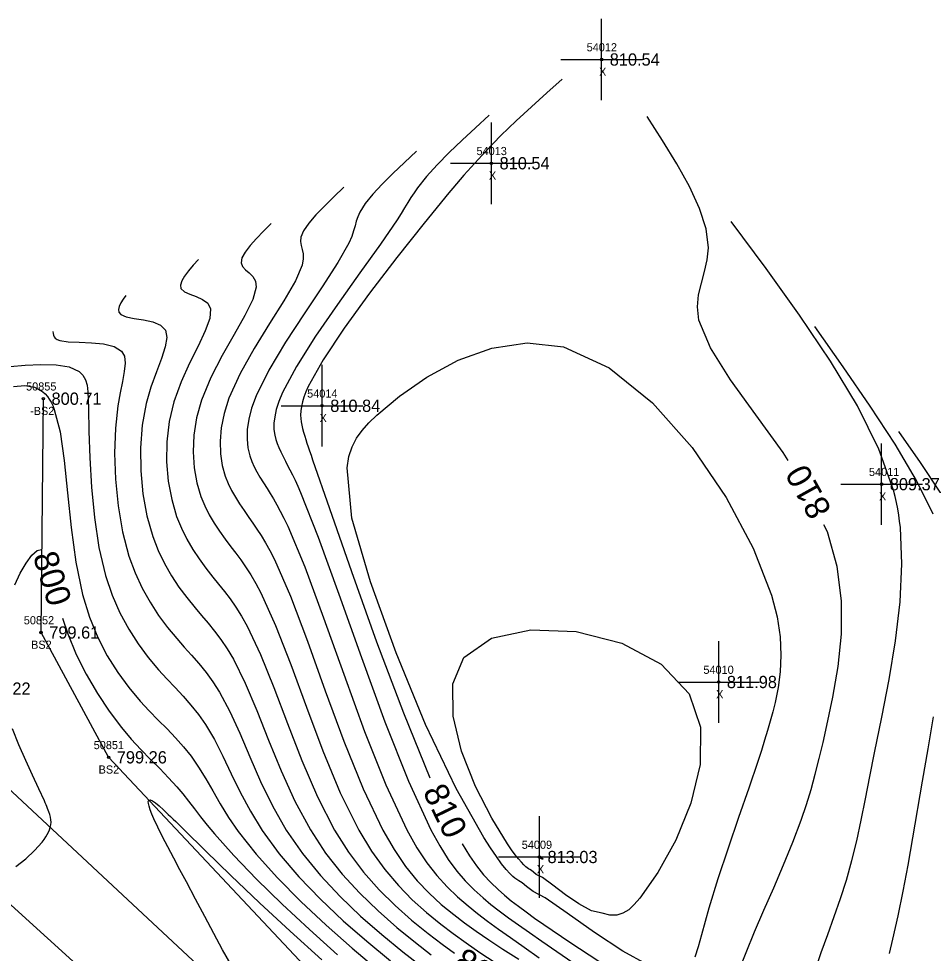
# Model space of a CAD drawing. Extents: x 1378535 to 1380697, y 997729 to 1000024.
# Drawn here: x 1378635.2 to 1378746.7, y 999909.1 to 1000023.6 of the extents above; entities that cross this region are included whole.
import ezdxf

# ---------------------------------------------------------------- set-up
doc = ezdxf.new("R2010")
doc.units = 0
for name, color, linetype in [('RD_DTM_BkLn1', 7, 'Continuous'), ('RD_DTM_BkLn2', 7, 'Continuous'), ('RD_DTM_BkLn_txCode', 7, 'Continuous'), ('RD_DTM_Major1', 7, 'Continuous'), ('RD_DTM_Major1_Lbl', 7, 'Continuous'), ('RD_DTM_Minor1', 7, 'Continuous'), ('RD_EX_Misc', 7, 'Continuous'), ('RD_EX_Misc_txCode', 7, 'Continuous'), ('RD_EX_Road', 7, 'Continuous'), ('RD_EX_TX_Misc_ELEV', 7, 'Continuous'), ('RD_SMD_Locator', 7, 'Continuous')]:
    doc.layers.add(name, color=color, linetype=linetype)

msp = doc.modelspace()

# ---------------------------------------------------------------- linework, layer by layer
at = {"layer": 'RD_DTM_BkLn1'}
msp.add_lwpolyline([(1379201.7, 999398.21), (1379156.53, 999438.89), (1379112.08, 999479.85), (1379066.5, 999520.56), (1379020.82, 999562.61), (1378974.24, 999604.98), (1378928.96, 999646.78), (1378882.74, 999688.62), (1378834.58, 999733.07), (1378787.7, 999775.12), (1378743.64, 999816.27), (1378698.71, 999856.43), (1378652.06, 999898.79), (1378607.02, 999939.65), (1378604.54, 999941.27)], dxfattribs=at)
at = {"layer": 'RD_DTM_BkLn2'}
msp.add_lwpolyline([(1378843.62, 999885.07), (1378833.28, 999869.8), (1378802.97, 999829.09), (1378773.74, 999822.49), (1378758.68, 999830.54), (1378715.18, 999866.67), (1378674.59, 999902.83), (1378646.18, 999933.08), (1378637.9, 999948.38), (1378638.18, 999977.04)], dxfattribs=at)
at = {"layer": 'RD_DTM_Major1'}
for points in [[(1378701.77, 1000016.22), (1378699.89, 1000014.53), (1378698.01, 1000012.83), (1378696.14, 1000011.09), (1378694.28, 1000009.29), (1378692.44, 1000007.4), (1378690.61, 1000005.43), (1378690.18, 1000004.93), (1378689.73, 1000004.42), (1378689.29, 1000003.91), (1378688.84, 1000003.37), (1378688.37, 1000002.83), (1378687.9, 1000002.26), (1378684.85, 999998.54), (1378681.51, 999994.36), (1378678.16, 999989.99), (1378675.06, 999985.7), (1378672.47, 999981.79), (1378670.66, 999978.54), (1378670.35, 999977.86), (1378670.11, 999977.23), (1378669.93, 999976.64), (1378669.81, 999976.08), (1378669.74, 999975.54), (1378669.72, 999975.01), (1378669.74, 999974.62), (1378669.78, 999974.22), (1378669.86, 999973.8), (1378669.95, 999973.37), (1378670.07, 999972.92), (1378670.22, 999972.43), (1378670.35, 999972.02), (1378670.49, 999971.59), (1378670.65, 999971.13), (1378670.82, 999970.63), (1378671, 999970.11), (1378671.19, 999969.55), (1378673.25, 999963.58), (1378675.94, 999955.87), (1378679.03, 999947.23), (1378682.32, 999938.51), (1378685.56, 999930.56)], [(1378729.51, 999969.45), (1378728.87, 999970.46), (1378725.55, 999975.06), (1378722.44, 999979.36), (1378719.96, 999983.26), (1378718.56, 999986.67), (1378718.38, 999988.29), (1378718.52, 999989.79), (1378718.85, 999991.22), (1378719.25, 999992.62), (1378719.58, 999994.05), (1378719.73, 999995.54), (1378719.44, 999997.85), (1378718.63, 1000000.37), (1378717.4, 1000003.04), (1378715.84, 1000005.83), (1378714.08, 1000008.7), (1378712.21, 1000011.62)], [(1378657.19, 999994.11), (1378656.56, 999993.41), (1378655.98, 999992.72), (1378655.49, 999992.07), (1378655.14, 999991.48), (1378654.98, 999990.96), (1378655.05, 999990.53), (1378655.47, 999990.15), (1378656.14, 999989.85), (1378656.93, 999989.56), (1378657.7, 999989.21), (1378658.33, 999988.74), (1378658.68, 999988.06), (1378658.6, 999986.88), (1378658.03, 999985.34), (1378657.15, 999983.49), (1378656.11, 999981.39), (1378655.07, 999979.1), (1378654.19, 999976.66), (1378653.62, 999974.23), (1378653.33, 999971.76), (1378653.29, 999969.31), (1378653.5, 999966.94), (1378653.91, 999964.68), (1378654.52, 999962.6), (1378655.1, 999961.15), (1378655.76, 999959.82), (1378656.49, 999958.57), (1378657.28, 999957.39), (1378658.11, 999956.27), (1378658.97, 999955.17), (1378659.67, 999954.31), (1378660.37, 999953.42), (1378661.07, 999952.49), (1378661.78, 999951.49), (1378662.48, 999950.38), (1378663.18, 999949.15), (1378664.81, 999945.7), (1378666.43, 999941.64), (1378668.11, 999937.22), (1378669.88, 999932.67), (1378671.79, 999928.23), (1378673.88, 999924.16), (1378675.6, 999921.43), (1378677.43, 999919.01), (1378679.34, 999916.85), (1378681.32, 999914.9), (1378683.33, 999913.13), (1378685.36, 999911.49), (1378687.07, 999910.17), (1378688.6, 999909.05)], [(1378723.7, 999907.53), (1378724.34, 999909.16), (1378725.38, 999911.67), (1378726.53, 999914.33), (1378727.73, 999917.08), (1378728.93, 999919.88), (1378730.06, 999922.66), (1378731.08, 999925.37), (1378731.73, 999927.28), (1378732.3, 999929.15), (1378732.82, 999931.03), (1378733.3, 999932.93), (1378733.77, 999934.9), (1378734.23, 999936.96), (1378734.98, 999940.46), (1378735.62, 999944.21), (1378736.02, 999948.17), (1378736.02, 999952.28), (1378735.5, 999956.47), (1378734.3, 999960.7), (1378733.87, 999961.59)], [(1378634.67, 999954.21), (1378635.35, 999955.64), (1378636.07, 999956.89), (1378636.78, 999957.85), (1378637.43, 999958.44), (1378637.93, 999958.56)], [(1378640.53, 999950.13), (1378641.17, 999948.22), (1378642.22, 999945.7), (1378643.44, 999943.26), (1378644.8, 999940.91), (1378646.24, 999938.72), (1378647.74, 999936.74), (1378648.94, 999935.32), (1378650.13, 999934.03), (1378651.31, 999932.83), (1378652.44, 999931.69), (1378653.53, 999930.57), (1378654.56, 999929.45), (1378655.29, 999928.59), (1378655.99, 999927.7), (1378656.71, 999926.77), (1378657.46, 999925.8), (1378658.27, 999924.78), (1378659.16, 999923.69), (1378661.52, 999921.04), (1378664.32, 999918.14), (1378667.44, 999915.09), (1378670.79, 999911.96), (1378674.25, 999908.88)], [(1378634.8, 999919.69), (1378636.01, 999920.65), (1378637.1, 999921.67), (1378638.02, 999922.68), (1378638.26, 999923), (1378638.47, 999923.31), (1378638.66, 999923.62), (1378638.81, 999923.91), (1378638.94, 999924.2), (1378639.03, 999924.48), (1378639.1, 999924.8), (1378639.12, 999925.12), (1378639.11, 999925.43), (1378639.06, 999925.75), (1378638.97, 999926.07), (1378638.86, 999926.41), (1378638.78, 999926.61), (1378638.7, 999926.82), (1378638.61, 999927.04), (1378638.51, 999927.27), (1378638.41, 999927.5), (1378638.3, 999927.75), (1378637.62, 999929.2), (1378636.85, 999930.88), (1378636.01, 999932.7), (1378635.18, 999934.62), (1378634.4, 999936.57)], [(1378689.51, 999922.47), (1378689.51, 999922.46), (1378690.41, 999921.01), (1378691.29, 999919.76), (1378692.16, 999918.69), (1378693.03, 999917.74), (1378693.93, 999916.87), (1378694.71, 999916.18), (1378695.54, 999915.5), (1378696.42, 999914.82), (1378697.38, 999914.12), (1378698.41, 999913.38), (1378699.54, 999912.59), (1378702.71, 999910.41), (1378706.28, 999908.08)]]:
    msp.add_lwpolyline(points, dxfattribs=at)
at = {"layer": 'RD_DTM_Minor1'}
for points in [[(1378692.85, 1000011.79), (1378691.16, 1000010.25), (1378689.51, 1000008.72), (1378687.93, 1000007.21), (1378686.47, 1000005.72), (1378685.16, 1000004.28), (1378684.05, 1000002.88), (1378683.64, 1000002.28), (1378683.25, 1000001.69), (1378682.86, 1000001.07), (1378682.46, 1000000.42), (1378682.03, 999999.73), (1378681.54, 999998.97), (1378679.51, 999995.99), (1378676.98, 999992.45), (1378674.24, 999988.59), (1378671.56, 999984.69), (1378669.23, 999981), (1378667.51, 999977.78), (1378667.06, 999976.7), (1378666.74, 999975.72), (1378666.54, 999974.83), (1378666.44, 999974.02), (1378666.45, 999973.26), (1378666.54, 999972.56), (1378666.66, 999972.05), (1378666.83, 999971.55), (1378667.04, 999971.05), (1378667.28, 999970.53), (1378667.56, 999969.97), (1378667.87, 999969.38), (1378668.13, 999968.86), (1378668.41, 999968.31), (1378668.71, 999967.7), (1378669.03, 999967.04), (1378669.36, 999966.32), (1378669.72, 999965.52), (1378671.87, 999960.06), (1378674.4, 999953.09), (1378677.17, 999945.31), (1378680.06, 999937.43), (1378682.94, 999930.15), (1378685.68, 999924.18), (1378686.77, 999922.22), (1378687.82, 999920.56), (1378688.87, 999919.14), (1378689.91, 999917.93), (1378690.98, 999916.85), (1378692.08, 999915.86), (1378693.05, 999915.05), (1378694.08, 999914.25), (1378695.2, 999913.42), (1378696.42, 999912.55), (1378697.77, 999911.6), (1378699.28, 999910.55), (1378703.62, 999907.56)], [(1378683.94, 1000007.37), (1378682.46, 1000006), (1378681.04, 1000004.66), (1378679.73, 1000003.35), (1378678.58, 1000002.11), (1378677.64, 1000000.96), (1378676.98, 999999.91), (1378676.73, 999999.34), (1378676.54, 999998.79), (1378676.39, 999998.22), (1378676.22, 999997.6), (1378675.98, 999996.92), (1378675.65, 999996.12), (1378674.3, 999993.73), (1378672.38, 999990.77), (1378670.14, 999987.45), (1378667.86, 999983.98), (1378665.81, 999980.55), (1378664.25, 999977.37), (1378663.71, 999975.88), (1378663.36, 999974.51), (1378663.18, 999973.25), (1378663.15, 999972.09), (1378663.26, 999971.03), (1378663.48, 999970.05), (1378663.72, 999969.36), (1378664.01, 999968.7), (1378664.35, 999968.06), (1378664.73, 999967.41), (1378665.15, 999966.73), (1378665.61, 999966.02), (1378665.99, 999965.41), (1378666.38, 999964.76), (1378666.8, 999964.04), (1378667.23, 999963.26), (1378667.68, 999962.39), (1378668.14, 999961.42), (1378670.22, 999956.43), (1378672.53, 999950.19), (1378675, 999943.27), (1378677.57, 999936.25), (1378680.17, 999929.69), (1378682.74, 999924.18), (1378683.98, 999922), (1378685.21, 999920.15), (1378686.43, 999918.57), (1378687.68, 999917.2), (1378688.95, 999915.99), (1378690.26, 999914.86), (1378691.41, 999913.94), (1378692.64, 999913.01), (1378693.97, 999912.03), (1378695.45, 999910.98), (1378697.11, 999909.82), (1378698.98, 999908.51)], [(1378675.02, 1000002.95), (1378673.8, 1000001.79), (1378672.64, 1000000.65), (1378671.6, 999999.56), (1378670.72, 999998.54), (1378670.09, 999997.62), (1378669.74, 999996.82), (1378669.69, 999996.3), (1378669.77, 999995.82), (1378669.9, 999995.34), (1378670.02, 999994.8), (1378670.05, 999994.17), (1378669.92, 999993.4), (1378669.09, 999991.48), (1378667.67, 999989.04), (1378665.91, 999986.24), (1378664.04, 999983.21), (1378662.29, 999980.12), (1378660.93, 999977.09), (1378660.34, 999975.24), (1378659.99, 999973.48), (1378659.85, 999971.82), (1378659.9, 999970.28), (1378660.11, 999968.85), (1378660.47, 999967.54), (1378660.83, 999966.63), (1378661.24, 999965.77), (1378661.72, 999964.95), (1378662.24, 999964.14), (1378662.8, 999963.33), (1378663.39, 999962.49), (1378663.87, 999961.8), (1378664.37, 999961.06), (1378664.89, 999960.26), (1378665.42, 999959.38), (1378665.96, 999958.41), (1378666.52, 999957.32), (1378668.47, 999952.82), (1378670.55, 999947.31), (1378672.74, 999941.24), (1378675.02, 999935.06), (1378677.38, 999929.21), (1378679.78, 999924.15), (1378681.17, 999921.76), (1378682.58, 999919.71), (1378684.01, 999917.95), (1378685.46, 999916.41), (1378686.96, 999915.05), (1378688.49, 999913.79), (1378689.82, 999912.77), (1378691.24, 999911.75), (1378692.78, 999910.69), (1378694.51, 999909.56), (1378696.46, 999908.32)], [(1378666.1, 999998.53), (1378665.17, 999997.59), (1378664.29, 999996.67), (1378663.52, 999995.8), (1378662.91, 999995), (1378662.53, 999994.29), (1378662.42, 999993.69), (1378662.59, 999993.23), (1378662.96, 999992.84), (1378663.41, 999992.45), (1378663.85, 999992), (1378664.17, 999991.45), (1378664.27, 999990.72), (1378663.85, 999989.19), (1378662.89, 999987.22), (1378661.57, 999984.91), (1378660.11, 999982.35), (1378658.71, 999979.64), (1378657.57, 999976.87), (1378656.97, 999974.7), (1378656.64, 999972.57), (1378656.55, 999970.52), (1378656.67, 999968.56), (1378657, 999966.73), (1378657.49, 999965.05), (1378657.96, 999963.89), (1378658.5, 999962.8), (1378659.1, 999961.78), (1378659.76, 999960.8), (1378660.45, 999959.83), (1378661.18, 999958.87), (1378661.77, 999958.09), (1378662.37, 999957.28), (1378662.98, 999956.41), (1378663.6, 999955.46), (1378664.23, 999954.4), (1378664.86, 999953.23), (1378666.65, 999949.25), (1378668.5, 999944.47), (1378670.43, 999939.24), (1378672.45, 999933.87), (1378674.58, 999928.73), (1378676.84, 999924.14), (1378678.41, 999921.56), (1378680.03, 999919.32), (1378681.7, 999917.35), (1378683.41, 999915.62), (1378685.16, 999914.06), (1378686.93, 999912.62), (1378688.44, 999911.46), (1378690.02, 999910.32), (1378691.71, 999909.16), (1378693.56, 999907.94)], [(1378732.81, 999906.99), (1378733.56, 999909.16), (1378734.35, 999911.35), (1378735.14, 999913.55), (1378735.92, 999915.78), (1378736.63, 999918.02), (1378737.3, 999920.41), (1378737.9, 999922.85), (1378738.45, 999925.37), (1378738.98, 999927.99), (1378739.52, 999930.73), (1378740.09, 999933.62), (1378740.98, 999938.01), (1378741.86, 999942.63), (1378742.64, 999947.37), (1378743.21, 999952.13), (1378743.44, 999956.79), (1378743.25, 999961.24), (1378743.16, 999962.01), (1378743.05, 999962.78), (1378742.92, 999963.54), (1378742.77, 999964.3), (1378742.6, 999965.06), (1378742.4, 999965.82), (1378740.6, 999970.87), (1378737.98, 999976.16), (1378734.69, 999981.63), (1378730.9, 999987.26), (1378726.78, 999992.98), (1378722.49, 999998.74)], [(1378648.27, 999989.69), (1378647.96, 999989.23), (1378647.69, 999988.78), (1378647.49, 999988.35), (1378647.39, 999987.97), (1378647.44, 999987.63), (1378647.66, 999987.36), (1378648.34, 999987.07), (1378649.33, 999986.88), (1378650.47, 999986.7), (1378651.59, 999986.45), (1378652.54, 999986.06), (1378653.16, 999985.45), (1378653.33, 999984.56), (1378653.12, 999983.39), (1378652.65, 999981.97), (1378652.03, 999980.33), (1378651.36, 999978.47), (1378650.77, 999976.44), (1378650.3, 999973.81), (1378650.08, 999971.03), (1378650.11, 999968.2), (1378650.38, 999965.39), (1378650.87, 999962.68), (1378651.58, 999960.16), (1378652.25, 999958.42), (1378653.02, 999956.82), (1378653.88, 999955.33), (1378654.8, 999953.95), (1378655.77, 999952.65), (1378656.77, 999951.42), (1378657.56, 999950.47), (1378658.37, 999949.52), (1378659.16, 999948.54), (1378659.95, 999947.5), (1378660.73, 999946.36), (1378661.49, 999945.1), (1378662.94, 999942.18), (1378664.36, 999938.83), (1378665.8, 999935.18), (1378667.34, 999931.42), (1378669.02, 999927.7), (1378670.91, 999924.17), (1378672.77, 999921.34), (1378674.8, 999918.76), (1378676.96, 999916.41), (1378679.21, 999914.24), (1378681.5, 999912.23), (1378683.8, 999910.36), (1378685.73, 999908.87)], [(1378747.27, 999962.9), (1378745.22, 999967.03), (1378742.6, 999971.47), (1378739.56, 999976.14), (1378736.24, 999980.96), (1378732.77, 999985.87)], [(1378639.35, 999985.27), (1378639.37, 999985.04), (1378639.41, 999984.83), (1378639.49, 999984.62), (1378639.64, 999984.44), (1378639.87, 999984.28), (1378640.21, 999984.16), (1378641.23, 999984.02), (1378642.57, 999983.96), (1378644.08, 999983.9), (1378645.56, 999983.75), (1378646.84, 999983.44), (1378647.75, 999982.88), (1378648.11, 999982.24), (1378648.2, 999981.4), (1378648.1, 999980.37), (1378647.87, 999979.16), (1378647.58, 999977.76), (1378647.31, 999976.17), (1378647.01, 999973.42), (1378646.91, 999970.38), (1378647.02, 999967.16), (1378647.34, 999963.9), (1378647.88, 999960.73), (1378648.66, 999957.75), (1378649.42, 999955.69), (1378650.29, 999953.81), (1378651.26, 999952.08), (1378652.31, 999950.48), (1378653.41, 999949.01), (1378654.55, 999947.63), (1378655.45, 999946.6), (1378656.36, 999945.58), (1378657.25, 999944.56), (1378658.12, 999943.49), (1378658.97, 999942.34), (1378659.78, 999941.08), (1378661.05, 999938.7), (1378662.27, 999936.02), (1378663.5, 999933.13), (1378664.81, 999930.13), (1378666.27, 999927.11), (1378667.94, 999924.16), (1378669.93, 999921.28), (1378672.16, 999918.57), (1378674.56, 999916.02), (1378677.08, 999913.62), (1378679.67, 999911.36), (1378682.25, 999909.25), (1378684.41, 999907.56)], [(1378698.22, 999916.62), (1378697.43, 999917.26), (1378696.87, 999917.68), (1378696.49, 999917.94), (1378696.21, 999918.12), (1378695.99, 999918.27), (1378695.75, 999918.47), (1378695.38, 999918.82), (1378694.92, 999919.34), (1378694.36, 999920.03), (1378693.72, 999920.91), (1378692.99, 999921.97), (1378692.18, 999923.24), (1378688.81, 999929.27), (1378685.02, 999937.08), (1378681.45, 999945.87), (1378678.3, 999954.59), (1378676, 999962.41), (1378675.44, 999968.55), (1378675.64, 999969.94), (1378676.02, 999971.14), (1378676.56, 999972.2), (1378677.26, 999973.16), (1378678.1, 999974.09), (1378679.08, 999975.02), (1378681.86, 999977.35), (1378685.21, 999979.69), (1378689.02, 999981.75), (1378693.16, 999983.25), (1378697.51, 999983.89), (1378701.95, 999983.38), (1378707.53, 999980.83), (1378712.85, 999976.54), (1378717.71, 999971.05), (1378721.89, 999964.92), (1378725.21, 999958.71), (1378727.44, 999952.97), (1378728.13, 999950.28), (1378728.5, 999947.84), (1378728.61, 999945.61), (1378728.51, 999943.55), (1378728.25, 999941.62), (1378727.88, 999939.79), (1378727.6, 999938.66), (1378727.3, 999937.52), (1378726.97, 999936.37), (1378726.61, 999935.17), (1378726.21, 999933.92), (1378725.77, 999932.58), (1378724.66, 999929.31), (1378723.42, 999925.71), (1378722.14, 999921.94), (1378720.89, 999918.17), (1378719.77, 999914.57), (1378718.85, 999911.31), (1378718.46, 999909.84), (1378718.06, 999908.59)], [(1378634.11, 999981), (1378635.94, 999981.15), (1378637.87, 999981.24), (1378639.73, 999981.2), (1378641.35, 999980.94), (1378642.58, 999980.39), (1378643.03, 999979.94), (1378643.33, 999979.37), (1378643.53, 999978.68), (1378643.64, 999977.87), (1378643.69, 999976.92), (1378643.72, 999975.84), (1378643.77, 999973.05), (1378643.87, 999969.77), (1378644.07, 999966.19), (1378644.43, 999962.48), (1378644.99, 999958.81), (1378645.8, 999955.36), (1378646.61, 999952.97), (1378647.57, 999950.79), (1378648.64, 999948.8), (1378649.81, 999946.99), (1378651.04, 999945.33), (1378652.31, 999943.82), (1378653.32, 999942.7), (1378654.33, 999941.62), (1378655.31, 999940.56), (1378656.27, 999939.48), (1378657.19, 999938.34), (1378658.05, 999937.11), (1378659.14, 999935.26), (1378660.18, 999933.23), (1378661.22, 999931.06), (1378662.32, 999928.79), (1378663.56, 999926.46), (1378664.99, 999924.12), (1378667.09, 999921.24), (1378669.5, 999918.42), (1378672.15, 999915.68), (1378674.95, 999913.04), (1378677.84, 999910.52), (1378680.72, 999908.13)], [(1378634.53, 999978.55), (1378635.89, 999978.67), (1378637.1, 999978.45), (1378638.13, 999977.88), (1378638.41, 999977.62), (1378638.67, 999977.32), (1378638.91, 999976.98), (1378639.13, 999976.6), (1378639.33, 999976.19), (1378639.52, 999975.73), (1378640.23, 999972.96), (1378640.74, 999969.47), (1378641.15, 999965.48), (1378641.59, 999961.25), (1378642.16, 999957.02), (1378642.98, 999953.02), (1378643.83, 999950.27), (1378644.85, 999947.77), (1378646.02, 999945.51), (1378647.3, 999943.47), (1378648.66, 999941.63), (1378650.05, 999939.98), (1378651.17, 999938.78), (1378652.27, 999937.65), (1378653.35, 999936.56), (1378654.39, 999935.48), (1378655.38, 999934.37), (1378656.3, 999933.21), (1378657.21, 999931.88), (1378658.08, 999930.46), (1378658.95, 999928.95), (1378659.87, 999927.37), (1378660.89, 999925.71), (1378662.07, 999923.99), (1378664.27, 999921.19), (1378666.87, 999918.31), (1378669.76, 999915.4), (1378672.84, 999912.51), (1378676.02, 999909.7), (1378679.2, 999907.03)], [(1378748.23, 999965.46), (1378745.7, 999969.2), (1378743.05, 999973)], [(1378698.6, 999918.71), (1378698.27, 999919.01), (1378698.02, 999919.2), (1378697.83, 999919.33), (1378697.67, 999919.42), (1378697.51, 999919.52), (1378697.34, 999919.65), (1378697.09, 999919.88), (1378696.78, 999920.21), (1378696.43, 999920.63), (1378696.02, 999921.14), (1378695.57, 999921.75), (1378695.09, 999922.46), (1378693.15, 999925.6), (1378691.16, 999929.51), (1378689.46, 999933.82), (1378688.42, 999938.14), (1378688.39, 999942.1), (1378689.73, 999945.32), (1378693.11, 999947.69), (1378697.95, 999948.72), (1378703.52, 999948.49), (1378709.09, 999947.06), (1378713.94, 999944.49), (1378717.35, 999940.86), (1378718.73, 999936.77), (1378718.69, 999932.19), (1378717.57, 999927.46), (1378715.73, 999922.94), (1378713.53, 999918.94), (1378711.31, 999915.82), (1378710.62, 999915.03), (1378709.94, 999914.4), (1378709.24, 999913.96), (1378708.49, 999913.72), (1378707.65, 999913.72), (1378706.69, 999913.99), (1378705.38, 999914.25), (1378703.82, 999915.1), (1378702.18, 999916.24), (1378700.64, 999917.41), (1378699.39, 999918.33), (1378698.6, 999918.71)], [(1378741.9, 999909.02), (1378742.34, 999910.8), (1378742.98, 999913.65), (1378743.6, 999916.68), (1378744.19, 999919.87), (1378744.77, 999923.19), (1378745.97, 999930.15), (1378746.65, 999934.1), (1378747.33, 999938.05)], [(1378661.19, 999907.64), (1378660.15, 999909.46), (1378659.07, 999911.46), (1378657.96, 999913.56), (1378656.84, 999915.69), (1378655.72, 999917.81), (1378654.92, 999919.3), (1378654.16, 999920.73), (1378653.44, 999922.09), (1378652.78, 999923.35), (1378652.2, 999924.5), (1378651.72, 999925.54), (1378651.47, 999926.12), (1378651.27, 999926.63), (1378651.13, 999927.07), (1378651.05, 999927.43), (1378651.04, 999927.68), (1378651.11, 999927.83), (1378651.28, 999927.86), (1378651.55, 999927.74), (1378651.91, 999927.5), (1378652.36, 999927.13), (1378652.89, 999926.65), (1378653.49, 999926.08), (1378653.78, 999925.81), (1378654.08, 999925.51), (1378654.4, 999925.21), (1378654.73, 999924.88), (1378655.07, 999924.54), (1378655.43, 999924.19), (1378658.05, 999921.62), (1378661.17, 999918.59), (1378664.68, 999915.25), (1378668.43, 999911.75), (1378672.3, 999908.24)], [(1378698.98, 999920.8), (1378698.94, 999920.82), (1378698.94, 999920.83), (1378698.93, 999920.84), (1378698.93, 999920.84), (1378698.94, 999920.84), (1378698.94, 999920.84), (1378698.95, 999920.85), (1378698.97, 999920.85), (1378699, 999920.85), (1378699.03, 999920.85), (1378699.07, 999920.84), (1378699.11, 999920.82), (1378699.17, 999920.8), (1378699.22, 999920.78), (1378699.28, 999920.75), (1378699.33, 999920.72), (1378699.37, 999920.69), (1378699.41, 999920.66), (1378699.43, 999920.63), (1378699.45, 999920.61), (1378699.45, 999920.59), (1378699.44, 999920.58), (1378699.41, 999920.58), (1378699.37, 999920.59), (1378699.35, 999920.6), (1378699.33, 999920.6), (1378699.3, 999920.61), (1378699.28, 999920.63), (1378699.22, 999920.66), (1378699.18, 999920.68), (1378699.13, 999920.7), (1378699.09, 999920.73), (1378699.04, 999920.76), (1378699.01, 999920.78), (1378698.98, 999920.8)], [(1378712.2, 999907.68), (1378709.21, 999909.3), (1378705.76, 999911.6), (1378702.41, 999913.98), (1378699.71, 999915.86), (1378698.22, 999916.62)]]:
    msp.add_lwpolyline(points, dxfattribs=at)
at = {"layer": 'RD_EX_Misc'}
for p, q in [((1378706.62, 1000013.62), (1378706.62, 1000023.62)), ((1378701.62, 1000018.62), (1378711.62, 1000018.62)), ((1378693.11, 1000000.9), (1378693.11, 1000010.9)), ((1378688.11, 1000005.9), (1378698.11, 1000005.9)), ((1378672.35, 999971.17), (1378672.35, 999981.17)), ((1378667.35, 999976.17), (1378677.35, 999976.17)), ((1378740.95, 999961.56), (1378740.95, 999971.56)), ((1378735.95, 999966.56), (1378745.95, 999966.56)), ((1378720.98, 999937.31), (1378720.98, 999947.31)), ((1378715.98, 999942.31), (1378725.98, 999942.31)), ((1378698.99, 999915.86), (1378698.99, 999925.86)), ((1378693.99, 999920.86), (1378703.99, 999920.86))]:
    msp.add_line(p, q, dxfattribs=at)
at = {"layer": 'RD_EX_Road'}
msp.add_lwpolyline([(1379209.48, 999405.54), (1379164, 999446.49), (1379118.81, 999488.02), (1379074.41, 999528.84), (1379028.67, 999569.9), (1378981.98, 999612.72), (1378937.17, 999653.91), (1378890.13, 999696.79), (1378842.57, 999740.72), (1378794.88, 999783.08), (1378749.81, 999824.15), (1378706.23, 999863.66), (1378659.58, 999905.32), (1378614.06, 999947.76), (1378610.31, 999950.38)], dxfattribs=at)
at = {"layer": 'RD_SMD_Locator'}
for centre in [(1378706.62, 1000018.62), (1378693.11, 1000005.9), (1378638.18, 999977.04), (1378672.35, 999976.17), (1378740.95, 999966.56), (1378637.9, 999948.38), (1378720.98, 999942.31), (1378646.18, 999933.08), (1378698.99, 999920.86)]:
    msp.add_circle(centre, 0.15, dxfattribs=at)

# ---------------------------------------------------------------- texts
at = {"layer": 'RD_DTM_BkLn_txCode'}
for s, p in [('50855', (1378636.06, 999978.04)), ('-BS2', (1378636.55, 999975.04)), ('50852', (1378635.78, 999949.38)), ('BS2', (1378636.67, 999946.38)), ('50851', (1378644.35, 999934.08)), ('BS2', (1378644.95, 999931.08))]:
    msp.add_text(s, height=1, dxfattribs=at).set_placement(p)
at = {"layer": 'RD_DTM_Major1_Lbl'}
for s, rotation, p in [('810', 119.0273, (1378734.89, 999963.41)), ('800', 287.1837, (1378636.87, 999957.77)), ('810', 295.9829, (1378684.64, 999928.88)), ('805', 326.4738, (1378688.23, 999907.41))]:
    msp.add_text(s, height=3, rotation=rotation, dxfattribs=at).set_placement(p)
at = {"layer": 'RD_EX_Misc_txCode'}
for s, p in [('54012', (1378704.79, 1000019.62)), ('X', (1378706.31, 1000016.62)), ('54013', (1378691.28, 1000006.9)), ('X', (1378692.8, 1000003.9)), ('54014', (1378670.52, 999977.17)), ('X', (1378672.04, 999974.17)), ('54011', (1378739.4, 999967.56)), ('X', (1378740.63, 999964.56)), ('54010', (1378719.1, 999943.31)), ('X', (1378720.66, 999940.31)), ('54009', (1378696.83, 999921.86)), ('X', (1378698.68, 999918.86))]:
    msp.add_text(s, height=1, dxfattribs=at).set_placement(p)
at = {"layer": 'RD_EX_TX_Misc_ELEV'}
for s, p in [('810.54', (1378707.62, 1000017.87)), ('810.54', (1378694.11, 1000005.15)), ('800.71', (1378639.18, 999976.29)), ('810.84', (1378673.35, 999975.42)), ('809.37', (1378741.95, 999965.81)), ('799.61', (1378638.9, 999947.63)), ('800.22', (1378630.48, 999940.75)), ('811.98', (1378721.98, 999941.56)), ('799.26', (1378647.18, 999932.33)), ('813.03', (1378699.99, 999920.11))]:
    msp.add_text(s, height=1.5, dxfattribs=at).set_placement(p)

doc.saveas('drawing.dxf')
